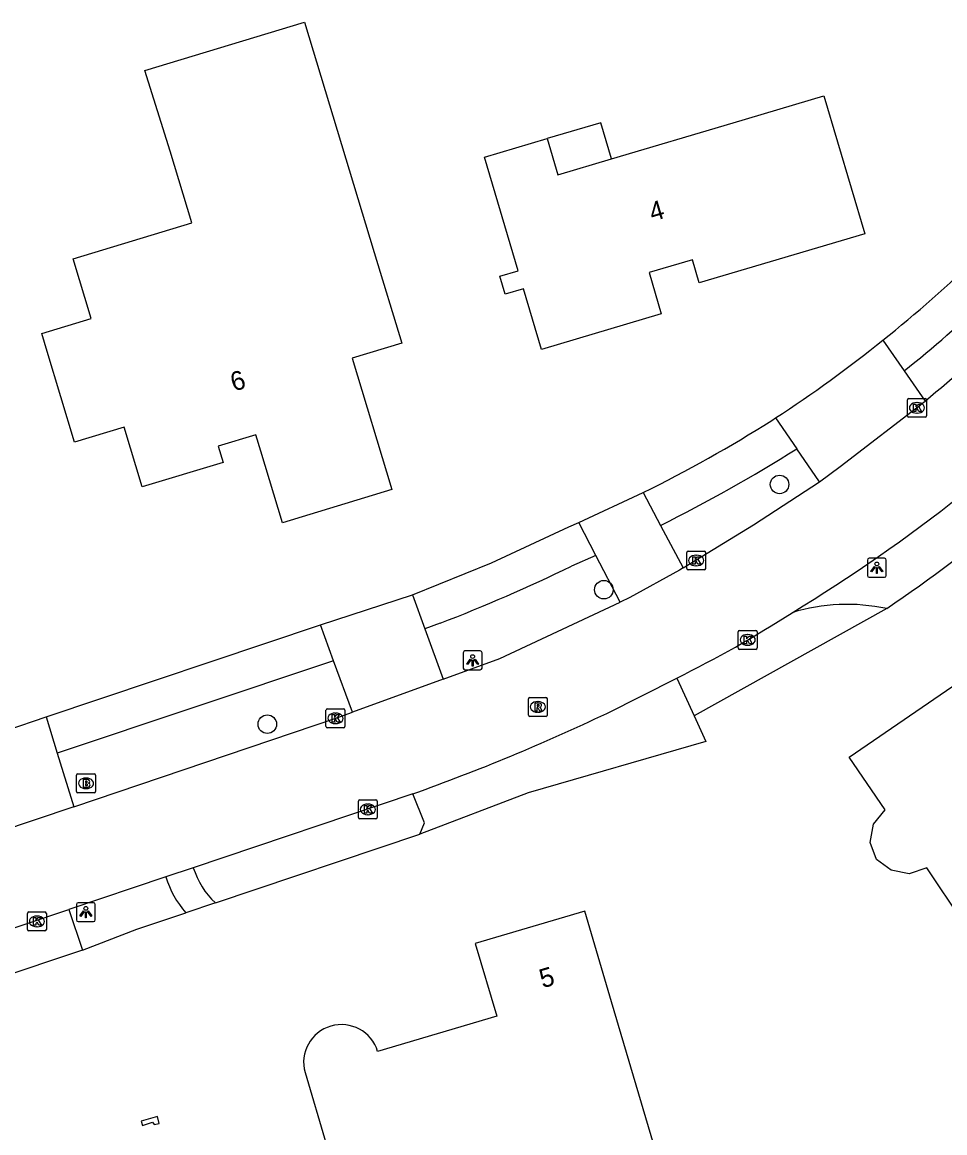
# Model space of a CAD drawing. Extents: x 162417 to 163721, y 384268 to 385416.
# Drawn here: x 163373.9 to 163422.7, y 384594.2 to 384652.8 of the extents above; entities that cross this region are included whole.
import ezdxf

# ---------------------------------------------------------------- set-up
doc = ezdxf.new("R2010")
doc.units = 0
for name, color, linetype in [('IMGEO_Boom', 7, 'Continuous'), ('IMGEO_Brandkraan', 7, 'Continuous'), ('IMGEO_Groenvoorziening', 7, 'Continuous'), ('IMGEO_Kolk', 7, 'Continuous'), ('IMGEO_Lichtpunt', 7, 'Continuous'), ('IMGEO_Pand', 7, 'Continuous'), ('IMGEO_Pand_nummerreeks', 7, 'Continuous'), ('IMGEO_Pand_overbouw', 7, 'Continuous'), ('IMGEO_Rijbaan_lokaal_open', 7, 'Continuous'), ('IMGEO_Rioolput', 7, 'Continuous'), ('IMGEO_Voetpad_open', 7, 'Continuous')]:
    doc.layers.add(name, color=color, linetype=linetype)

msp = doc.modelspace()

# ---------------------------------------------------------------- linework, layer by layer
at = {"layer": 'IMGEO_Boom'}
for centre in [(163413.924, 384628.428), (163404.643, 384622.873), (163386.868, 384615.776)]:
    msp.add_circle(centre, 0.489, dxfattribs=at)
at = {"layer": 'IMGEO_Brandkraan'}
for p, q in [((163376.793, 384612.228), (163376.793, 384613.08)), ((163376.868, 384613.154), (163377.72, 384613.154)), ((163377.281, 384612.934), (163377.306, 384612.934)), ((163377.794, 384613.08), (163377.794, 384612.228)), ((163377.304, 384612.374), (163377.279, 384612.374)), ((163377.72, 384612.154), (163376.868, 384612.154))]:
    msp.add_line(p, q, dxfattribs=at)
for points in [[(163376.793, 384612.228), (163376.793, 384613.08)], [(163376.868, 384613.154), (163377.72, 384613.154)], [(163377.141, 384612.854), (163377.141, 384612.454), (163377.354, 384612.454)], [(163377.372, 384612.854), (163377.141, 384612.854)], [(163377.32, 384612.773), (163377.266, 384612.773), (163377.266, 384612.697)], [(163377.794, 384613.08), (163377.794, 384612.228)], [(163377.266, 384612.697), (163377.319, 384612.697)], [(163377.328, 384612.621), (163377.266, 384612.621), (163377.266, 384612.54)], [(163377.266, 384612.54), (163377.328, 384612.54)], [(163377.72, 384612.154), (163376.868, 384612.154)]]:
    msp.add_lwpolyline(points, dxfattribs=at)
for centre, radius, start, end in [((163376.87, 384613.078), 0.0765, 91.55205, 178.44795), ((163376.87, 384613.078), 0.0765, 91.55205, 178.44795), ((163377.321, 384612.735), 0.0379, 267.82845, 90.93552), ((163377.376, 384612.709), 0.145, 59.4692, 91.53667), ((163377.401, 384612.756), 0.0922, 285.51372, 58.15012), ((163377.718, 384613.078), 0.0765, 1.55205, 88.44795), ((163377.718, 384613.078), 0.0765, 1.55205, 88.44795), ((163376.87, 384612.23), 0.0765, 181.55205, 268.44795), ((163376.87, 384612.23), 0.0765, 181.55205, 268.44795), ((163377.329, 384612.58), 0.0404, 269.87594, 90.50774), ((163377.36, 384612.705), 0.251, 268.66757, 293.53466), ((163377.406, 384612.564), 0.105, 301.31148, 78.98903), ((163377.718, 384612.23), 0.0765, 271.55205, 358.44795), ((163377.718, 384612.23), 0.0765, 271.55205, 358.44795)]:
    msp.add_arc(centre, radius, start, end, dxfattribs=at)
for centre, major_axis, ratio, start_param, end_param in [((163377.28, 384612.654), (-0.387, 0.002), 0.722429, 4.712389, 7.853982), ((163377.305, 384612.654), (-0.39, 0.002), 0.717154, 1.570796, 4.712389)]:
    msp.add_ellipse(centre, major_axis=major_axis, ratio=ratio, start_param=start_param, end_param=end_param, dxfattribs=at)
at = {"layer": 'IMGEO_Groenvoorziening'}
for points in [[(163419.582, 384621.874), (163409.408, 384616.22)], [(163384.126, 384606.347), (163394.917, 384609.966)], [(163377.103, 384603.845), (163379.98, 384604.957), (163382.571, 384605.826)]]:
    msp.add_lwpolyline(points, dxfattribs=at)
at = {"layer": 'IMGEO_Kolk'}
for p, q in [((163420.679, 384632.046), (163420.679, 384632.898)), ((163420.754, 384632.972), (163421.606, 384632.972)), ((163421.167, 384632.752), (163421.192, 384632.752)), ((163421.68, 384632.898), (163421.68, 384632.046)), ((163421.19, 384632.192), (163421.165, 384632.192)), ((163421.606, 384631.972), (163420.754, 384631.972)), ((163409.019, 384623.988), (163409.019, 384624.84)), ((163409.094, 384624.914), (163409.946, 384624.914)), ((163409.507, 384624.694), (163409.532, 384624.694)), ((163410.02, 384624.84), (163410.02, 384623.988)), ((163409.946, 384623.914), (163409.094, 384623.914)), ((163409.53, 384624.134), (163409.505, 384624.134)), ((163411.74, 384619.798), (163411.74, 384620.65)), ((163411.815, 384620.724), (163412.667, 384620.724)), ((163412.228, 384620.504), (163412.253, 384620.504)), ((163412.741, 384620.65), (163412.741, 384619.798)), ((163412.251, 384619.944), (163412.226, 384619.944)), ((163412.667, 384619.724), (163411.815, 384619.724)), ((163389.968, 384615.659), (163389.968, 384616.511)), ((163390.043, 384616.585), (163390.895, 384616.585)), ((163390.456, 384616.365), (163390.481, 384616.365)), ((163390.969, 384616.511), (163390.969, 384615.659)), ((163390.479, 384615.805), (163390.454, 384615.805)), ((163390.895, 384615.585), (163390.043, 384615.585)), ((163391.677, 384610.854), (163391.677, 384611.706)), ((163391.752, 384611.78), (163392.604, 384611.78)), ((163392.678, 384611.706), (163392.678, 384610.854)), ((163392.165, 384611.56), (163392.19, 384611.56)), ((163392.604, 384610.78), (163391.752, 384610.78)), ((163392.188, 384611), (163392.163, 384611)), ((163374.2, 384604.941), (163374.2, 384605.793)), ((163374.275, 384605.867), (163375.127, 384605.867)), ((163375.201, 384605.793), (163375.201, 384604.941)), ((163374.688, 384605.647), (163374.713, 384605.647)), ((163375.127, 384604.867), (163374.275, 384604.867)), ((163374.711, 384605.087), (163374.686, 384605.087))]:
    msp.add_line(p, q, dxfattribs=at)
for points in [[(163420.679, 384632.046), (163420.679, 384632.898)], [(163420.754, 384632.972), (163421.606, 384632.972)], [(163421.68, 384632.898), (163421.68, 384632.046)], [(163421, 384632.672), (163421.123, 384632.672), (163421.123, 384632.521), (163421.253, 384632.672), (163421.417, 384632.672), (163421.271, 384632.521), (163421.424, 384632.272), (163421.272, 384632.272), (163421.187, 384632.436), (163421.123, 384632.369), (163421.123, 384632.272), (163421, 384632.272), (163421, 384632.672)], [(163421.606, 384631.972), (163420.754, 384631.972)], [(163409.019, 384623.988), (163409.019, 384624.84)], [(163409.094, 384624.914), (163409.946, 384624.914)], [(163409.34, 384624.614), (163409.463, 384624.614), (163409.463, 384624.463), (163409.593, 384624.614), (163409.757, 384624.614), (163409.611, 384624.463), (163409.764, 384624.214), (163409.612, 384624.214), (163409.527, 384624.378), (163409.463, 384624.311), (163409.463, 384624.214), (163409.34, 384624.214), (163409.34, 384624.614)], [(163410.02, 384624.84), (163410.02, 384623.988)], [(163409.946, 384623.914), (163409.094, 384623.914)], [(163411.74, 384619.798), (163411.74, 384620.65)], [(163411.815, 384620.724), (163412.667, 384620.724)], [(163412.061, 384620.424), (163412.184, 384620.424), (163412.184, 384620.273), (163412.314, 384620.424), (163412.478, 384620.424), (163412.332, 384620.273), (163412.485, 384620.024), (163412.333, 384620.024), (163412.248, 384620.188), (163412.184, 384620.121), (163412.184, 384620.024), (163412.061, 384620.024), (163412.061, 384620.424)], [(163412.741, 384620.65), (163412.741, 384619.798)], [(163412.667, 384619.724), (163411.815, 384619.724)], [(163389.968, 384615.659), (163389.968, 384616.511)], [(163390.043, 384616.585), (163390.895, 384616.585)], [(163390.289, 384616.285), (163390.412, 384616.285), (163390.412, 384616.134), (163390.542, 384616.285), (163390.706, 384616.285), (163390.56, 384616.134), (163390.713, 384615.885), (163390.561, 384615.885), (163390.476, 384616.049), (163390.412, 384615.982), (163390.412, 384615.885), (163390.289, 384615.885), (163390.289, 384616.285)], [(163390.969, 384616.511), (163390.969, 384615.659)], [(163390.895, 384615.585), (163390.043, 384615.585)], [(163391.677, 384610.854), (163391.677, 384611.706)], [(163391.752, 384611.78), (163392.604, 384611.78)], [(163392.678, 384611.706), (163392.678, 384610.854)], [(163391.998, 384611.48), (163392.121, 384611.48), (163392.121, 384611.329), (163392.251, 384611.48), (163392.415, 384611.48), (163392.269, 384611.329), (163392.422, 384611.08), (163392.27, 384611.08), (163392.185, 384611.244), (163392.121, 384611.177), (163392.121, 384611.08), (163391.998, 384611.08), (163391.998, 384611.48)], [(163392.604, 384610.78), (163391.752, 384610.78)], [(163374.2, 384604.941), (163374.2, 384605.793)], [(163374.275, 384605.867), (163375.127, 384605.867)], [(163375.201, 384605.793), (163375.201, 384604.941)], [(163374.521, 384605.567), (163374.644, 384605.567), (163374.644, 384605.416), (163374.774, 384605.567), (163374.938, 384605.567), (163374.792, 384605.416), (163374.945, 384605.167), (163374.793, 384605.167), (163374.708, 384605.331), (163374.644, 384605.264), (163374.644, 384605.167), (163374.521, 384605.167), (163374.521, 384605.567)], [(163375.127, 384604.867), (163374.275, 384604.867)]]:
    msp.add_lwpolyline(points, dxfattribs=at)
for centre, start, end in [((163420.756, 384632.896), 91.55205, 178.44795), ((163420.756, 384632.896), 91.55205, 178.44795), ((163421.604, 384632.896), 1.55205, 88.44795), ((163421.604, 384632.896), 1.55205, 88.44795), ((163420.756, 384632.048), 181.55205, 268.44795), ((163420.756, 384632.048), 181.55205, 268.44795), ((163421.604, 384632.048), 271.55205, 358.44795), ((163421.604, 384632.048), 271.55205, 358.44795), ((163409.096, 384624.838), 91.55205, 178.44795), ((163409.096, 384624.838), 91.55205, 178.44795), ((163409.944, 384624.838), 1.55205, 88.44795), ((163409.944, 384624.838), 1.55205, 88.44795), ((163409.096, 384623.99), 181.55205, 268.44795), ((163409.096, 384623.99), 181.55205, 268.44795), ((163409.944, 384623.99), 271.55205, 358.44795), ((163409.944, 384623.99), 271.55205, 358.44795), ((163411.817, 384620.648), 91.55205, 178.44795), ((163411.817, 384620.648), 91.55205, 178.44795), ((163412.665, 384620.648), 1.55205, 88.44795), ((163412.665, 384620.648), 1.55205, 88.44795), ((163411.817, 384619.8), 181.55205, 268.44795), ((163411.817, 384619.8), 181.55205, 268.44795), ((163412.665, 384619.8), 271.55205, 358.44795), ((163412.665, 384619.8), 271.55205, 358.44795), ((163390.045, 384616.509), 91.55205, 178.44795), ((163390.045, 384616.509), 91.55205, 178.44795), ((163390.893, 384616.509), 1.55205, 88.44795), ((163390.893, 384616.509), 1.55205, 88.44795), ((163390.045, 384615.661), 181.55205, 268.44795), ((163390.045, 384615.661), 181.55205, 268.44795), ((163390.893, 384615.661), 271.55205, 358.44795), ((163390.893, 384615.661), 271.55205, 358.44795), ((163391.754, 384611.704), 91.55205, 178.44795), ((163391.754, 384611.704), 91.55205, 178.44795), ((163392.602, 384611.704), 1.55205, 88.44795), ((163392.602, 384611.704), 1.55205, 88.44795), ((163391.754, 384610.856), 181.55205, 268.44795), ((163391.754, 384610.856), 181.55205, 268.44795), ((163392.602, 384610.856), 271.55205, 358.44795), ((163392.602, 384610.856), 271.55205, 358.44795), ((163374.277, 384605.791), 91.55205, 178.44795), ((163374.277, 384605.791), 91.55205, 178.44795), ((163375.125, 384605.791), 1.55205, 88.44795), ((163375.125, 384605.791), 1.55205, 88.44795), ((163374.277, 384604.943), 181.55205, 268.44795), ((163374.277, 384604.943), 181.55205, 268.44795), ((163375.125, 384604.943), 271.55205, 358.44795), ((163375.125, 384604.943), 271.55205, 358.44795)]:
    msp.add_arc(centre, 0.0765, start, end, dxfattribs=at)
for centre, major_axis, ratio, start_param, end_param in [((163421.166, 384632.472), (-0.387, 0.002), 0.722429, 4.712389, 7.853982), ((163421.191, 384632.472), (-0.39, 0.002), 0.717154, 1.570796, 4.712389), ((163409.506, 384624.414), (-0.387, 0.002), 0.722429, 4.712389, 7.853982), ((163409.531, 384624.414), (-0.39, 0.002), 0.717154, 1.570796, 4.712389), ((163412.227, 384620.224), (-0.387, 0.002), 0.722429, 4.712389, 7.853982), ((163412.252, 384620.224), (-0.39, 0.002), 0.717154, 1.570796, 4.712389), ((163390.455, 384616.085), (-0.387, 0.002), 0.722429, 4.712389, 7.853982), ((163390.48, 384616.085), (-0.39, 0.002), 0.717154, 1.570796, 4.712389), ((163392.164, 384611.28), (-0.387, 0.002), 0.722429, 4.712389, 7.853982), ((163392.189, 384611.28), (-0.39, 0.002), 0.717154, 1.570796, 4.712389), ((163374.687, 384605.367), (-0.387, 0.002), 0.722429, 4.712389, 7.853982), ((163374.712, 384605.367), (-0.39, 0.002), 0.717154, 1.570796, 4.712389)]:
    msp.add_ellipse(centre, major_axis=major_axis, ratio=ratio, start_param=start_param, end_param=end_param, dxfattribs=at)
at = {"layer": 'IMGEO_Lichtpunt'}
for p, q in [((163419.464, 384624.53), (163418.656, 384624.53)), ((163419.464, 384624.53), (163418.656, 384624.53)), ((163418.562, 384624.435), (163418.562, 384623.628)), ((163418.562, 384624.435), (163418.562, 384623.628)), ((163419.558, 384623.628), (163419.558, 384624.435)), ((163419.558, 384623.628), (163419.558, 384624.435)), ((163418.656, 384623.534), (163419.464, 384623.534)), ((163418.656, 384623.534), (163419.464, 384623.534)), ((163397.215, 384619.545), (163397.215, 384618.738)), ((163397.215, 384619.545), (163397.215, 384618.738)), ((163398.117, 384619.64), (163397.309, 384619.64)), ((163398.117, 384619.64), (163397.309, 384619.64)), ((163398.211, 384618.738), (163398.211, 384619.545)), ((163398.211, 384618.738), (163398.211, 384619.545)), ((163397.309, 384618.644), (163398.117, 384618.644)), ((163397.309, 384618.644), (163398.117, 384618.644)), ((163377.689, 384606.351), (163376.881, 384606.351)), ((163377.689, 384606.351), (163376.881, 384606.351)), ((163376.787, 384606.256), (163376.787, 384605.449)), ((163376.787, 384606.256), (163376.787, 384605.449)), ((163377.783, 384605.449), (163377.783, 384606.256)), ((163377.783, 384605.449), (163377.783, 384606.256)), ((163376.881, 384605.355), (163377.689, 384605.355)), ((163376.881, 384605.355), (163377.689, 384605.355))]:
    msp.add_line(p, q, dxfattribs=at)
for points in [[(163418.936, 384624.099), (163418.975, 384624.071), (163418.787, 384623.809), (163418.749, 384623.836), (163418.936, 384624.099)], [(163419.038, 384624.051), (163419.085, 384624.051), (163419.085, 384623.729), (163419.038, 384623.729), (163419.038, 384624.051)], [(163419.148, 384624.071), (163419.186, 384624.098), (163419.373, 384623.836), (163419.334, 384623.808), (163419.148, 384624.071)], [(163397.589, 384619.209), (163397.628, 384619.181), (163397.44, 384618.919), (163397.402, 384618.946), (163397.589, 384619.209)], [(163397.691, 384619.161), (163397.738, 384619.161), (163397.738, 384618.839), (163397.691, 384618.839), (163397.691, 384619.161)], [(163397.801, 384619.181), (163397.839, 384619.208), (163398.026, 384618.946), (163397.987, 384618.918), (163397.801, 384619.181)], [(163377.161, 384605.92), (163377.2, 384605.892), (163377.012, 384605.63), (163376.974, 384605.657), (163377.161, 384605.92)], [(163377.263, 384605.872), (163377.31, 384605.872), (163377.31, 384605.55), (163377.263, 384605.55), (163377.263, 384605.872)], [(163377.373, 384605.892), (163377.411, 384605.919), (163377.598, 384605.657), (163377.559, 384605.629), (163377.373, 384605.892)]]:
    msp.add_lwpolyline(points, dxfattribs=at)
for centre in [(163419.061, 384624.233), (163397.714, 384619.343), (163377.286, 384606.054)]:
    msp.add_circle(centre, 0.0994, dxfattribs=at)
for centre, start, end in [((163418.656, 384624.435), 90, 180), ((163418.656, 384624.435), 90, 180), ((163419.464, 384624.435), 0, 90), ((163419.464, 384624.435), 0, 90), ((163418.656, 384623.628), 180, 270), ((163418.656, 384623.628), 180, 270), ((163419.464, 384623.628), 270, 0), ((163419.464, 384623.628), 270, 360), ((163397.309, 384619.545), 90, 180), ((163397.309, 384619.545), 90, 180), ((163398.117, 384619.545), 0, 90), ((163398.117, 384619.545), 0, 90), ((163397.309, 384618.738), 180, 270), ((163397.309, 384618.738), 180, 270), ((163398.117, 384618.738), 270, 0), ((163398.117, 384618.738), 270, 360), ((163376.881, 384606.256), 90, 180), ((163376.881, 384606.256), 90, 180), ((163377.689, 384606.256), 0, 90), ((163377.689, 384606.256), 0, 90), ((163376.881, 384605.449), 180, 270), ((163376.881, 384605.449), 180, 270), ((163377.689, 384605.449), 270, 0), ((163377.689, 384605.449), 270, 360)]:
    msp.add_arc(centre, 0.0946, start, end, dxfattribs=at)
at = {"layer": 'IMGEO_Pand'}
for points in [[(163392.516, 384640.667), (163393.965, 384635.882), (163391.345, 384635.089), (163393.445, 384628.155), (163387.663, 384626.41), (163386.518, 384630.192), (163386.261, 384631.043), (163384.28, 384630.444), (163384.538, 384629.593), (163380.261, 384628.298), (163379.31, 384631.443), (163376.692, 384630.651), (163375.243, 384635.437), (163374.953, 384636.394), (163377.573, 384637.187), (163376.623, 384640.332), (163382.891, 384642.229), (163381.746, 384646.012), (163380.405, 384650.271), (163388.837, 384652.823), (163392.516, 384640.667)], [(163416.266, 384648.938), (163418.425, 384641.662), (163409.685, 384639.076), (163409.329, 384640.29), (163407.033, 384639.616), (163407.664, 384637.439), (163401.35, 384635.549), (163400.4, 384638.751), (163399.431, 384638.464), (163399.146, 384639.421), (163400.114, 384639.709), (163398.338, 384645.7), (163401.655, 384646.683), (163402.221, 384644.775), (163405.042, 384645.611), (163411.472, 384647.517), (163416.266, 384648.938)], [(163423.426, 384619.015), (163423.504, 384619.857), (163425.24, 384621.047), (163426.06, 384620.847), (163426.722, 384620.31), (163434.524, 384625.652), (163437.361, 384621.535), (163444.73, 384610.844), (163436.077, 384604.88), (163431.875, 384610.985), (163423.588, 384605.386), (163421.696, 384608.187), (163420.775, 384607.881), (163419.813, 384608.066), (163419.044, 384608.641), (163418.702, 384609.538), (163418.883, 384610.501), (163419.499, 384611.264), (163417.6, 384614.035), (163423.689, 384618.208), (163423.426, 384619.015)], [(163388.86, 384597.387), (163389.971, 384593.627), (163387.17, 384592.799), (163388.587, 384588.004), (163389.04, 384586.469), (163401.957, 384590.287), (163403.019, 384586.69), (163408.811, 384588.401), (163405.052, 384601.119), (163403.635, 384605.913), (163397.853, 384604.204), (163398.987, 384600.369), (163392.697, 384598.51)], [(163380.278, 384594.593), (163380.806, 384594.769), (163380.887, 384594.646), (163381.162, 384594.702), (163381.068, 384595.07), (163380.213, 384594.822), (163380.278, 384594.593)]]:
    msp.add_lwpolyline(points, dxfattribs=at)
msp.add_arc((163390.786, 384597.921), 1.999, 17.12637, 195.50067, dxfattribs=at)
at = {"layer": 'IMGEO_Pand_overbouw'}
msp.add_lwpolyline([(163404.476, 384647.519), (163401.655, 384646.683), (163402.221, 384644.775), (163405.042, 384645.611)], close=True, dxfattribs=at)
at = {"layer": 'IMGEO_Rijbaan_lokaal_open'}
for points in [[(163416.038, 384628.57), (163417.131, 384629.372), (163421.605, 384632.827)], [(163408.832, 384624.02), (163412.543, 384626.296), (163416.038, 384628.57)], [(163408.832, 384624.02), (163408.641, 384623.903), (163406.014, 384622.456), (163405.506, 384622.218)], [(163396.153, 384618.151), (163399.158, 384619.244), (163405.506, 384622.218)], [(163396.153, 384618.151), (163391.36, 384616.408)], [(163404.799, 384616.348), (163408.495, 384618.212)], [(163376.658, 384611.416), (163390.546, 384616.112), (163391.36, 384616.408)], [(163394.546, 384612.095), (163382.96, 384608.203)], [(163376.658, 384611.416), (163372.594, 384610.058)], [(163382.96, 384608.203), (163381.515, 384607.717)], [(163381.515, 384607.717), (163376.389, 384605.995)], [(163371.696, 384604.423), (163376.389, 384605.995)]]:
    msp.add_lwpolyline(points, dxfattribs=at)
for centre, radius, start, end in [((163366.109, 384700.117), 87.222, 309.51339, 317.42123), ((163370.506, 384694.597), 85.221, 301.14686, 315.76166), ((163381.624, 384672.76), 60.808, 296.2254, 302.82367), ((163357.584, 384715.688), 109.99, 289.63659, 295.42129)]:
    msp.add_arc(centre, radius, start, end, dxfattribs=at)
at = {"layer": 'IMGEO_Rioolput'}
for p, q in [((163400.657, 384616.26), (163400.657, 384617.112)), ((163400.732, 384617.186), (163401.584, 384617.186)), ((163401.145, 384616.966), (163401.17, 384616.966)), ((163401.658, 384617.112), (163401.658, 384616.26)), ((163401.168, 384616.406), (163401.143, 384616.406)), ((163401.584, 384616.186), (163400.732, 384616.186))]:
    msp.add_line(p, q, dxfattribs=at)
for points in [[(163400.657, 384616.26), (163400.657, 384617.112)], [(163400.732, 384617.186), (163401.584, 384617.186)], [(163401.246, 384616.884), (163400.994, 384616.886), (163400.994, 384616.486)], [(163401.658, 384617.112), (163401.658, 384616.26)], [(163400.994, 384616.486), (163401.118, 384616.486), (163401.118, 384616.648), (163401.129, 384616.648)], [(163401.172, 384616.805), (163401.118, 384616.805), (163401.118, 384616.724)], [(163401.118, 384616.724), (163401.17, 384616.724)], [(163401.176, 384616.619), (163401.247, 384616.486), (163401.387, 384616.486), (163401.322, 384616.612)], [(163401.584, 384616.186), (163400.732, 384616.186)]]:
    msp.add_lwpolyline(points, dxfattribs=at)
for centre, radius, start, end in [((163400.734, 384617.11), 0.0765, 91.55205, 178.44795), ((163400.734, 384617.11), 0.0765, 91.55205, 178.44795), ((163401.245, 384616.774), 0.109, 350.36119, 89.41601), ((163401.582, 384617.11), 0.0765, 1.55205, 88.44795), ((163401.582, 384617.11), 0.0765, 1.55205, 88.44795), ((163401.128, 384616.595), 0.0533, 26.02933, 88.69889), ((163401.154, 384616.913), 0.19, 274.7715, 282.96867), ((163401.178, 384616.709), 0.0964, 77.00612, 93.18647), ((163401.192, 384616.766), 0.0378, 276.66336, 79.67722), ((163401.243, 384616.774), 0.112, 277.58423, 350.98172), ((163401.227, 384616.559), 0.108, 29.51342, 73.79051), ((163400.734, 384616.262), 0.0765, 181.55205, 268.44795), ((163400.734, 384616.262), 0.0765, 181.55205, 268.44795), ((163401.582, 384616.262), 0.0765, 271.55205, 358.44795), ((163401.582, 384616.262), 0.0765, 271.55205, 358.44795)]:
    msp.add_arc(centre, radius, start, end, dxfattribs=at)
for centre, major_axis, ratio, start_param, end_param in [((163401.144, 384616.686), (-0.387, 0.002), 0.722429, 4.712389, 7.853982), ((163401.169, 384616.686), (-0.39, 0.002), 0.717154, 1.570796, 4.712389)]:
    msp.add_ellipse(centre, major_axis=major_axis, ratio=ratio, start_param=start_param, end_param=end_param, dxfattribs=at)
at = {"layer": 'IMGEO_Voetpad_open'}
for points in [[(163419.383, 384636.043), (163420.504, 384634.421)], [(163420.504, 384634.421), (163421.605, 384632.827)], [(163413.514, 384631.806), (163413.713, 384631.935)], [(163413.713, 384631.935), (163414.832, 384630.315)], [(163416.038, 384628.57), (163414.832, 384630.315)], [(163403.314, 384626.415), (163406.716, 384627.995)], [(163406.716, 384627.995), (163407.636, 384626.267)], [(163394.532, 384622.596), (163398.708, 384624.299), (163402.801, 384626.194), (163403.314, 384626.415)], [(163404.226, 384624.67), (163403.314, 384626.415)], [(163407.636, 384626.267), (163408.832, 384624.02)], [(163404.226, 384624.67), (163402.927, 384624.111)], [(163405.506, 384622.218), (163404.226, 384624.67)], [(163389.679, 384621.017), (163394.532, 384622.596)], [(163394.532, 384622.596), (163395.186, 384620.803)], [(163375.186, 384616.159), (163389.679, 384621.017)], [(163390.37, 384619.126), (163389.679, 384621.017)], [(163395.999, 384621.107), (163395.186, 384620.803)], [(163395.186, 384620.803), (163396.153, 384618.151)], [(163390.37, 384619.126), (163375.772, 384614.24)], [(163391.36, 384616.408), (163390.37, 384619.126)], [(163408.495, 384618.212), (163409.408, 384616.22)], [(163371.048, 384614.758), (163375.186, 384616.159)], [(163375.186, 384616.159), (163375.772, 384614.24)], [(163409.408, 384616.22), (163410.03, 384614.861), (163400.639, 384612.147), (163394.917, 384609.966)], [(163375.772, 384614.24), (163376.658, 384611.416)], [(163394.917, 384609.966), (163395.176, 384610.568), (163394.546, 384612.095)], [(163384.126, 384606.347), (163382.571, 384605.826)], [(163376.389, 384605.995), (163377.103, 384603.845)], [(163377.103, 384603.845), (163372.405, 384602.287)]]:
    msp.add_lwpolyline(points, dxfattribs=at)
for centre, radius, start, end in [((163373.98, 384692.802), 72.684, 308.65684, 314.01186), ((163375.608, 384690.545), 71.872, 308.65738, 313.34994), ((163373.676, 384693.163), 73.156, 303.18096, 308.66682), ((163368.694, 384696.602), 90.409, 304.2543, 314.94032), ((163372.795, 384696.472), 76.418, 296.35239, 302.19812), ((163371.727, 384698.521), 80.685, 296.42647, 302.29206), ((163364.309, 384703.683), 88.448, 290.99513, 295.88824), ((163417.49, 384612.22), 9.878, 77.77644, 107.10513), ((163387.063, 384609.486), 4.299, 197.3688, 226.90797), ((163386.25, 384609.121), 4.939, 196.51369, 221.84733)]:
    msp.add_arc(centre, radius, start, end, dxfattribs=at)

# ---------------------------------------------------------------- texts
at = {"layer": 'IMGEO_Pand_nummerreeks'}
for s, rotation, p in [('4', 16.35795, (163407.207, 384642.293)), ('6', 16.82388, (163385.097, 384633.324)), ('5', 16.46623, (163401.41, 384601.834))]:
    msp.add_text(s, height=1, rotation=rotation, dxfattribs=at).set_placement(p)

doc.saveas('drawing.dxf')
